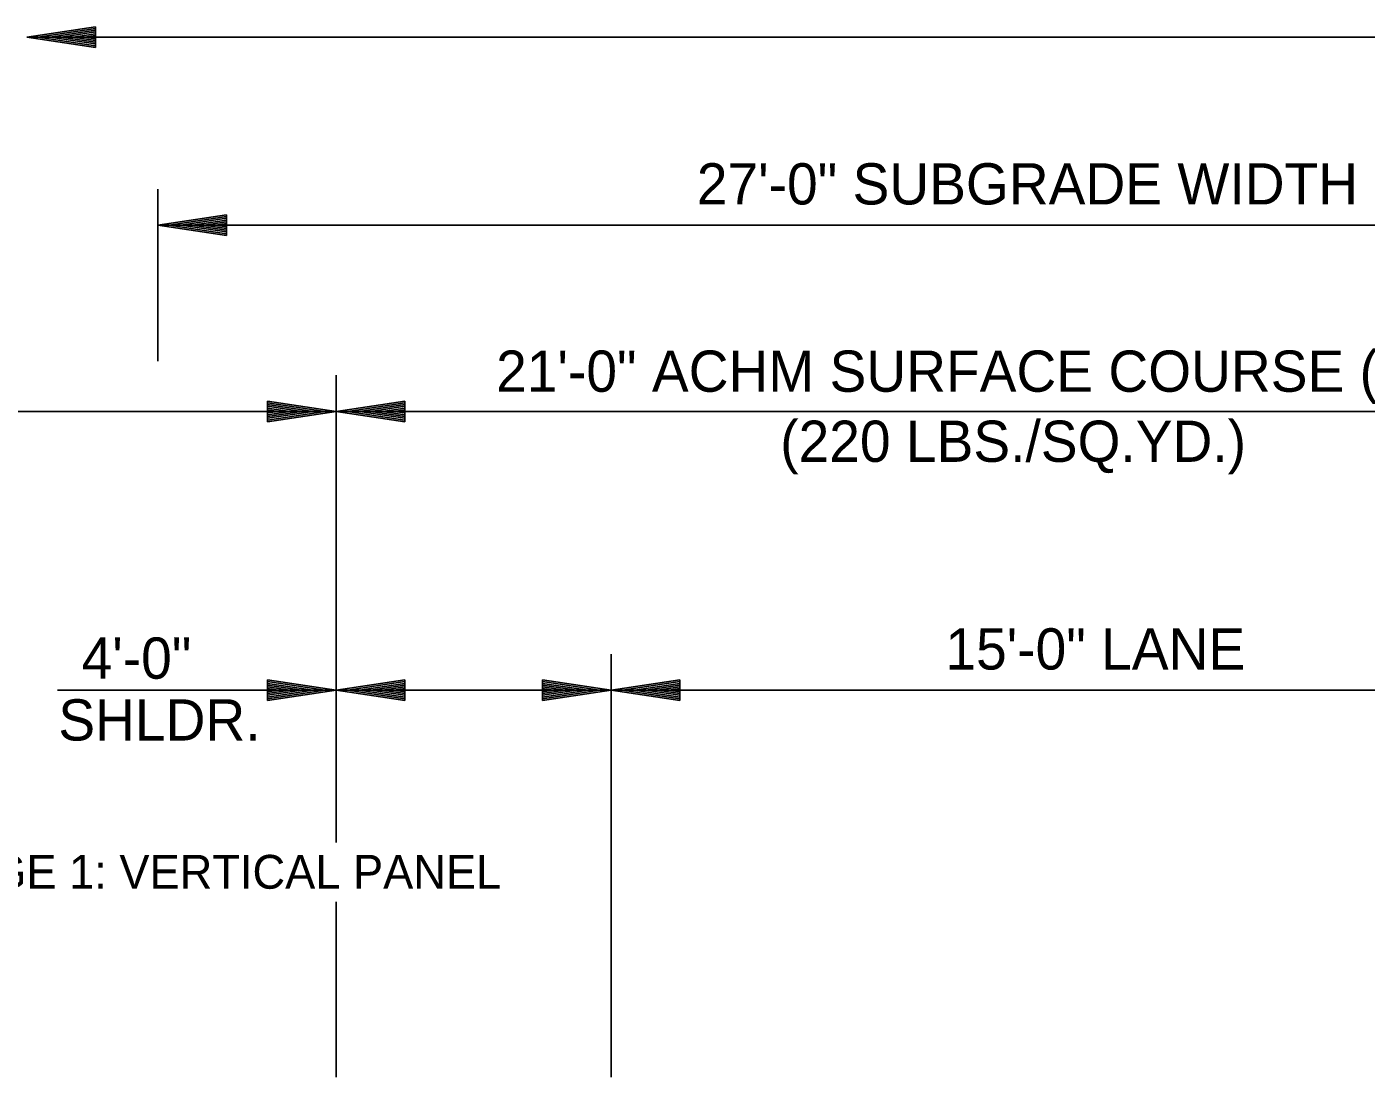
# Model space of a CAD drawing. Extents: x 2829243 to 2838161, y 467639 to 474695.
# Drawn here: x 2830390.5 to 2830585.4, y 467813.3 to 467966.1 of the extents above; entities that cross this region are included whole.
import ezdxf

# ---------------------------------------------------------------- set-up
doc = ezdxf.new("R2010")
doc.units = 0
doc.layers.add('R_Dimension', color=7, linetype='Continuous')
doc.layers.add('R_Draft', color=7, linetype='Continuous')

msp = doc.modelspace()

# ---------------------------------------------------------------- linework, layer by layer
at = {"layer": 'R_Dimension'}
for p, q in [((2830400.54, 467966.13), (2830390.54, 467964.63)), ((2830400.54, 467963.13), (2830400.54, 467966.13)), ((2830957.27, 467964.63), (2830390.54, 467964.63)), ((2830400.54, 467963.13), (2830390.54, 467964.63)), ((2830400.54, 467965.88), (2830392.21, 467964.63)), ((2830400.54, 467963.38), (2830392.21, 467964.63)), ((2830400.54, 467965.63), (2830393.93, 467964.63)), ((2830400.54, 467963.64), (2830393.93, 467964.63)), ((2830400.54, 467965.38), (2830395.59, 467964.63)), ((2830400.54, 467963.89), (2830395.59, 467964.63)), ((2830400.54, 467965.12), (2830397.29, 467964.63)), ((2830400.54, 467964.15), (2830397.29, 467964.63)), ((2830400.54, 467964.87), (2830398.96, 467964.63)), ((2830400.54, 467964.4), (2830398.96, 467964.63)), ((2830409.61, 467917.46), (2830409.61, 467942.53)), ((2830419.61, 467938.78), (2830409.61, 467937.28)), ((2830419.61, 467935.78), (2830419.61, 467938.78)), ((2830409.61, 467937.28), (2830674.83, 467937.28)), ((2830419.61, 467935.78), (2830409.61, 467937.28)), ((2830419.61, 467938.53), (2830411.28, 467937.28)), ((2830419.61, 467936.03), (2830411.28, 467937.28)), ((2830419.61, 467938.27), (2830413, 467937.28)), ((2830419.61, 467936.28), (2830413, 467937.28)), ((2830419.61, 467938.02), (2830414.67, 467937.28)), ((2830419.61, 467936.53), (2830414.67, 467937.28)), ((2830419.61, 467937.77), (2830416.36, 467937.28)), ((2830419.61, 467936.79), (2830416.36, 467937.28)), ((2830419.61, 467937.51), (2830418.03, 467937.28)), ((2830419.61, 467937.04), (2830418.03, 467937.28)), ((2830435.56, 467847.44), (2830435.56, 467915.43)), ((2830425.56, 467911.67), (2830435.56, 467910.17)), ((2830425.56, 467908.67), (2830425.56, 467911.67)), ((2830425.56, 467911.42), (2830433.89, 467910.17)), ((2830445.56, 467911.67), (2830435.56, 467910.17)), ((2830445.56, 467911.42), (2830437.23, 467910.17)), ((2830445.56, 467908.67), (2830445.56, 467911.67)), ((2830260.54, 467910.17), (2830435.56, 467910.17)), ((2830425.56, 467911.17), (2830432.17, 467910.17)), ((2830425.56, 467910.92), (2830430.51, 467910.17)), ((2830425.56, 467910.66), (2830428.81, 467910.17)), ((2830425.56, 467910.41), (2830427.14, 467910.17)), ((2830425.56, 467908.67), (2830435.56, 467910.17)), ((2830425.56, 467909.69), (2830428.81, 467910.17)), ((2830425.56, 467909.18), (2830432.17, 467910.17)), ((2830425.56, 467908.92), (2830433.89, 467910.17)), ((2830425.56, 467909.43), (2830430.51, 467910.17)), ((2830425.56, 467909.94), (2830427.14, 467910.17)), ((2830435.56, 467910.17), (2830645.56, 467910.17)), ((2830445.56, 467908.67), (2830435.56, 467910.17)), ((2830445.56, 467908.92), (2830437.23, 467910.17)), ((2830445.56, 467911.17), (2830438.95, 467910.17)), ((2830445.56, 467909.18), (2830438.95, 467910.17)), ((2830445.56, 467910.92), (2830440.62, 467910.17)), ((2830445.56, 467909.43), (2830440.62, 467910.17)), ((2830445.56, 467910.66), (2830442.31, 467910.17)), ((2830445.56, 467909.69), (2830442.31, 467910.17)), ((2830445.56, 467910.41), (2830443.98, 467910.17)), ((2830445.56, 467909.94), (2830443.98, 467910.17)), ((2830475.56, 467813.29), (2830475.56, 467874.86)), ((2830425.56, 467871.11), (2830435.56, 467869.61)), ((2830425.56, 467868.11), (2830425.56, 467871.11)), ((2830425.56, 467870.86), (2830433.89, 467869.61)), ((2830425.56, 467870.6), (2830432.17, 467869.61)), ((2830445.56, 467871.11), (2830435.56, 467869.61)), ((2830445.56, 467870.86), (2830437.23, 467869.61)), ((2830445.56, 467870.6), (2830438.95, 467869.61)), ((2830445.56, 467868.11), (2830445.56, 467871.11)), ((2830465.56, 467871.11), (2830475.56, 467869.61)), ((2830465.56, 467868.11), (2830465.56, 467871.11)), ((2830465.56, 467870.86), (2830473.89, 467869.61)), ((2830465.56, 467870.6), (2830472.17, 467869.61)), ((2830485.56, 467871.11), (2830475.56, 467869.61)), ((2830485.56, 467870.86), (2830477.23, 467869.61)), ((2830485.56, 467870.6), (2830478.95, 467869.61)), ((2830485.56, 467868.11), (2830485.56, 467871.11)), ((2830475.56, 467869.61), (2830394.99, 467869.61)), ((2830425.56, 467870.35), (2830430.51, 467869.61)), ((2830425.56, 467870.1), (2830428.81, 467869.61)), ((2830425.56, 467869.84), (2830427.14, 467869.61)), ((2830425.56, 467868.11), (2830435.56, 467869.61)), ((2830425.56, 467869.12), (2830428.81, 467869.61)), ((2830425.56, 467868.61), (2830432.17, 467869.61)), ((2830425.56, 467868.36), (2830433.89, 467869.61)), ((2830425.56, 467868.86), (2830430.51, 467869.61)), ((2830425.56, 467869.37), (2830427.14, 467869.61)), ((2830445.56, 467868.11), (2830435.56, 467869.61)), ((2830445.56, 467868.36), (2830437.23, 467869.61)), ((2830445.56, 467868.61), (2830438.95, 467869.61)), ((2830445.56, 467870.35), (2830440.62, 467869.61)), ((2830445.56, 467868.86), (2830440.62, 467869.61)), ((2830445.56, 467870.1), (2830442.31, 467869.61)), ((2830445.56, 467869.12), (2830442.31, 467869.61)), ((2830445.56, 467869.84), (2830443.98, 467869.61)), ((2830445.56, 467869.37), (2830443.98, 467869.61)), ((2830465.56, 467870.35), (2830470.51, 467869.61)), ((2830465.56, 467870.1), (2830468.81, 467869.61)), ((2830465.56, 467869.84), (2830467.14, 467869.61)), ((2830465.56, 467868.11), (2830475.56, 467869.61)), ((2830465.56, 467869.12), (2830468.81, 467869.61)), ((2830465.56, 467868.61), (2830472.17, 467869.61)), ((2830465.56, 467868.36), (2830473.89, 467869.61)), ((2830465.56, 467868.86), (2830470.51, 467869.61)), ((2830465.56, 467869.37), (2830467.14, 467869.61)), ((2830485.56, 467868.11), (2830475.56, 467869.61)), ((2830475.56, 467869.61), (2830625.56, 467869.61)), ((2830485.56, 467868.36), (2830477.23, 467869.61)), ((2830485.56, 467868.61), (2830478.95, 467869.61)), ((2830485.56, 467870.35), (2830480.62, 467869.61)), ((2830485.56, 467868.86), (2830480.62, 467869.61)), ((2830485.56, 467870.1), (2830482.31, 467869.61)), ((2830485.56, 467869.12), (2830482.31, 467869.61)), ((2830485.56, 467869.84), (2830483.98, 467869.61)), ((2830485.56, 467869.37), (2830483.98, 467869.61)), ((2830435.56, 467813.29), (2830435.56, 467838.82))]:
    msp.add_line(p, q, dxfattribs=at)

# ---------------------------------------------------------------- texts
for s, p in [('15\'-0" LANE', (2830524.2, 467872.61)), ('4\'-0"', (2830398.51, 467871.28)), ('SHLDR.', (2830395.13, 467862.28))]:
    msp.add_text(s, height=6, dxfattribs=at).set_placement(p)
at = {"layer": 'R_Draft'}
for s, height, p in [('27\'-0" SUBGRADE WIDTH', 6, (2830488.03, 467940.28)), ('21\'-0" ACHM SURFACE COURSE (1/2")', 6, (2830458.83, 467913.03)), ('(220 LBS./SQ.YD.)', 6, (2830500.17, 467902.83)), ('STAGE 1: VERTICAL PANEL', 4.9184, (2830372.58, 467840.72))]:
    msp.add_text(s, height=height, dxfattribs=at).set_placement(p)

doc.saveas('drawing.dxf')
